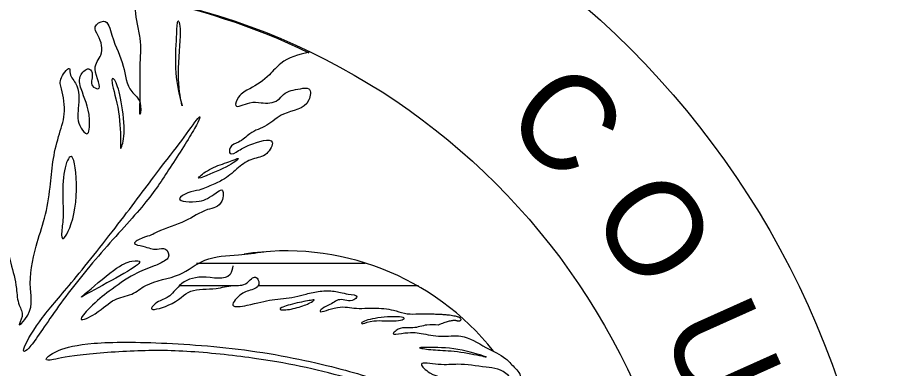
# Model space of a CAD drawing. Extents: x -1.6 to 33.4, y -12.7 to 10.9.
# Drawn here: x 27.0389 to 27.3212, y -12.2347 to -12.1203 of the extents above; entities that cross this region are included whole.
import ezdxf

# ---------------------------------------------------------------- set-up
doc = ezdxf.new("R2010")
doc.units = 0
doc.layers.add('Default', color=7, linetype='Continuous')

msp = doc.modelspace()

# ---------------------------------------------------------------- linework, layer by layer
at = {"layer": 'Default'}
for p, q in [((27.097185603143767, -12.200330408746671), (27.152113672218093, -12.200329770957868)), ((27.09167917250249, -12.20764956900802), (27.109073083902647, -12.207644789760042)), ((27.117312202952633, -12.207663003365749), (27.169493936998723, -12.207648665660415))]:
    msp.add_line(p, q, dxfattribs=at)
for radius in [0.28240568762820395, 0.2204114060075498]:
    msp.add_circle((27.03883012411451, -12.330318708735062), radius, dxfattribs=at)
for centre, radius, start, end in [((27.03811594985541, -12.33045840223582), 0.2204114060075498, 64.23515824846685, 79.6893776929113), ((27.12638568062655, -12.2824678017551), 0.08611740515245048, 38.42000269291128, 99.14313602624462)]:
    msp.add_arc(centre, radius, start, end, dxfattribs=at)
for points in [[(26.965344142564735, -12.171041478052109), (26.962602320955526, -12.165534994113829), (26.958024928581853, -12.16095770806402), (26.951621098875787, -12.155478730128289), (26.947945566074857, -12.153629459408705), (26.947954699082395, -12.151798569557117), (26.951616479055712, -12.151816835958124), (26.95893113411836, -12.153638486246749), (26.968094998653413, -12.156384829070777), (26.971752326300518, -12.157295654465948), (26.9754279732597, -12.159122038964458), (26.978169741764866, -12.160051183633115), (26.979080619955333, -12.160971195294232), (26.981817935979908, -12.162792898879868), (26.98000074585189, -12.160037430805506), (26.978165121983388, -12.156389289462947), (26.97540960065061, -12.153629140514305), (26.973587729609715, -12.151812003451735), (26.974512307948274, -12.14998568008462), (26.976338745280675, -12.150887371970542), (26.983648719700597, -12.153647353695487), (26.99099088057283, -12.159131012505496), (26.995563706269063, -12.164623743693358), (26.99831477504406, -12.168276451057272), (27.00196280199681, -12.16646371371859), (27.000136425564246, -12.160961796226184), (26.998305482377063, -12.156375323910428), (26.995568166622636, -12.154553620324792), (26.994638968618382, -12.152718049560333), (26.99647442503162, -12.151811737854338), (27.00288738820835, -12.155459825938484), (27.009291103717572, -12.160961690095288), (27.014774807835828, -12.167374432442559), (27.017525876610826, -12.171027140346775), (27.021197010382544, -12.178346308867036), (27.022098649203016, -12.171942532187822), (27.021187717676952, -12.166445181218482), (27.01935209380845, -12.162797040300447), (27.017530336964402, -12.160957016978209), (27.018454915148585, -12.159130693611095), (27.022112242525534, -12.16004151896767), (27.02668968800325, -12.169196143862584), (27.03127175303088, -12.182012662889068), (27.033999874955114, -12.190265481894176), (27.036764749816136, -12.200326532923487), (27.03857742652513, -12.208574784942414), (27.039511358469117, -12.214049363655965), (27.04040853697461, -12.217715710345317), (27.039502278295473, -12.220457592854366), (27.041342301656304, -12.218635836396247), (27.043154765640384, -12.208574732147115), (27.04498561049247, -12.194828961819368), (27.047731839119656, -12.185687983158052), (27.04956730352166, -12.175604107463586), (27.05047807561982, -12.167369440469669), (27.052327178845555, -12.159139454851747), (27.054148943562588, -12.151801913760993), (27.053228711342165, -12.143581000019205), (27.053224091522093, -12.139919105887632), (27.055984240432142, -12.137163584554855), (27.055979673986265, -12.138079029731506), (27.057815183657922, -12.141750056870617), (27.05873541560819, -12.149970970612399), (27.059641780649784, -12.15638376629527), (27.061463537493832, -12.158223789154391), (27.062378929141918, -12.15365101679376), (27.059637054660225, -12.143567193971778), (27.059637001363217, -12.138989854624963), (27.062392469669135, -12.13717266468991), (27.063298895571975, -12.138985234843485), (27.06330351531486, -12.142647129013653), (27.065129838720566, -12.143571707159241), (27.064223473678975, -12.137158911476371), (27.066054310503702, -12.132590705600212), (27.065125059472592, -12.126177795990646), (27.06422331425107, -12.123426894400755), (27.06695589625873, -12.121609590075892), (27.069702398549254, -12.126177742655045), (27.073382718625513, -12.136243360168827), (27.0761108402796, -12.144496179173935), (27.0788619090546, -12.148148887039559), (27.078866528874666, -12.151810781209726), (27.078875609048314, -12.145402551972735), (27.078875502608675, -12.136247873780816), (27.078875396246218, -12.12709319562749), (27.07795989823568, -12.122511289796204), (27.077044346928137, -12.113352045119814)], [(27.13380351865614, -12.131669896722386), (27.124630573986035, -12.13533178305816), (27.120973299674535, -12.138998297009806), (27.11456512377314, -12.143566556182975), (27.110912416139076, -12.146317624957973), (27.109983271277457, -12.149059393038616), (27.11456517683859, -12.148143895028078), (27.118227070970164, -12.148139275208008), (27.123724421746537, -12.147228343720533), (27.125564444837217, -12.145406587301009), (27.131043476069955, -12.143580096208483), (27.13378992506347, -12.14357090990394), (27.133794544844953, -12.147232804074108), (27.12555536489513, -12.15181481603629), (27.12006720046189, -12.1554721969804), (27.114560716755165, -12.158214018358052), (27.11090800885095, -12.160965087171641), (27.10815242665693, -12.162805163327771), (27.108166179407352, -12.164636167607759), (27.110917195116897, -12.163711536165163), (27.114565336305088, -12.16187591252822), (27.121893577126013, -12.160974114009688), (27.120067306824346, -12.164626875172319), (27.11548083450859, -12.166457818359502), (27.11091268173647, -12.169204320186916), (27.106339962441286, -12.172866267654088), (27.102668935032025, -12.174701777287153), (27.098082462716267, -12.176532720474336), (27.09443888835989, -12.17745289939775), (27.091683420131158, -12.179270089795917), (27.09808708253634, -12.180194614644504), (27.100838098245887, -12.179269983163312), (27.103593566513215, -12.177452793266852), (27.1054062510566, -12.176523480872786), (27.105410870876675, -12.18018537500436), (27.100842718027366, -12.182931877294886), (27.093523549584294, -12.186603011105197), (27.08435060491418, -12.190264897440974), (27.082538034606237, -12.191171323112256), (27.07978701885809, -12.192095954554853), (27.077031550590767, -12.19391314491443), (27.079773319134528, -12.194842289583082), (27.084368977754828, -12.195757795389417), (27.087115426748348, -12.195748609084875), (27.088017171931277, -12.198499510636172), (27.08709716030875, -12.199410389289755), (27.08344901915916, -12.201246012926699), (27.07702709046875, -12.203983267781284), (27.068806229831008, -12.209480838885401), (27.062393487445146, -12.214964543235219), (27.059651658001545, -12.218635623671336), (27.064215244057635, -12.216804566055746), (27.070623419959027, -12.212236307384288), (27.07612545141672, -12.2103870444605), (27.080693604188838, -12.207640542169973), (27.091674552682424, -12.203987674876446), (27.09991373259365, -12.19940566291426), (27.110908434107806, -12.197583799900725), (27.119152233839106, -12.196663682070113)], [(27.109082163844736, -12.201236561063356), (27.108152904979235, -12.204001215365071), (27.09901666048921, -12.204893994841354), (27.09167917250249, -12.20764956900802), (27.088021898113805, -12.211316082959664), (27.084350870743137, -12.213151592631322), (27.082533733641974, -12.214973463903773), (27.088031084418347, -12.214062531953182), (27.095354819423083, -12.20947595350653), (27.103575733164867, -12.20855572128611), (27.109073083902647, -12.207644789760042), (27.113654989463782, -12.206729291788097), (27.11641045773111, -12.204912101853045), (27.117321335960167, -12.205832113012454), (27.117312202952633, -12.207663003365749), (27.113664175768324, -12.209475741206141), (27.111828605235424, -12.210404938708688), (27.10908688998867, -12.214053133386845), (27.113664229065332, -12.214053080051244), (27.121889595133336, -12.212240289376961), (27.129217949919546, -12.211315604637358), (27.132884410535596, -12.210395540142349), (27.137466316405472, -12.209480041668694), (27.142043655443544, -12.209479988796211), (27.146616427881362, -12.210395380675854), (27.14935819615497, -12.211324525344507), (27.14843818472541, -12.212235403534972), (27.14386084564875, -12.212235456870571), (27.140212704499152, -12.214071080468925), (27.13837724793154, -12.214977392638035), (27.137457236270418, -12.2158882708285), (27.142039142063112, -12.214972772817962), (27.14844737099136, -12.214981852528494), (27.155771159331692, -12.21497261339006), (27.16217482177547, -12.215897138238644), (27.165832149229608, -12.216807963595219), (27.16949404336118, -12.216803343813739)], [(27.17590689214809, -12.22047431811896), (27.172244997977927, -12.220478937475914), (27.1676630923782, -12.221394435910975), (27.164916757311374, -12.22138073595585), (27.162165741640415, -12.22230536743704), (27.161245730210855, -12.2232162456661), (27.163992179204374, -12.223207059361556), (27.170400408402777, -12.223216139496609), (27.17682695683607, -12.224140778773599), (27.183235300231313, -12.224126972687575), (27.191456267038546, -12.227784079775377), (27.197869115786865, -12.231455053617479), (27.200624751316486, -12.23419231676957), (27.20246026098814, -12.237863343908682), (27.201540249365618, -12.23877422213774), (27.19878004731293, -12.23695240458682), (27.191470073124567, -12.23419242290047), (27.18231996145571, -12.233277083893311), (27.175911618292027, -12.233290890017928), (27.170418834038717, -12.23328637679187), (27.17315158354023, -12.236023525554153), (27.180489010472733, -12.23786817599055), (27.18688822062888, -12.239685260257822), (27.195131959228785, -12.243365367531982), (27.203366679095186, -12.24885347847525), (27.208864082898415, -12.252519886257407), (27.21161515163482, -12.256172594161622), (27.215258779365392, -12.259829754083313), (27.215272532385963, -12.261660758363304), (27.212516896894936, -12.258923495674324), (27.204286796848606, -12.25709727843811), (27.19787394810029, -12.25342630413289), (27.194221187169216, -12.251600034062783), (27.192385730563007, -12.25250634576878), (27.199714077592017, -12.260759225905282), (27.204286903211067, -12.266251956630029), (27.210681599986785, -12.273561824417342), (27.214348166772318, -12.281796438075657), (27.217108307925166, -12.288218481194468), (27.21802380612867, -12.292800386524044), (27.218010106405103, -12.295546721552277), (27.217094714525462, -12.30011949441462), (27.215259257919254, -12.301025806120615), (27.213446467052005, -12.292800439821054), (27.20428706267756, -12.279983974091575), (27.19878503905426, -12.272655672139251), (27.189634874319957, -12.26716299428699), (27.189630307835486, -12.268078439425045), (27.19328768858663, -12.27356660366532), (27.19879884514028, -12.279064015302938), (27.2015453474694, -12.28363216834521), (27.20335797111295, -12.287303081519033), (27.203371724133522, -12.289134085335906), (27.202442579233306, -12.291875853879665), (27.196958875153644, -12.2854631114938), (27.191456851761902, -12.27813480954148), (27.184146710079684, -12.2708203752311), (27.17864930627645, -12.267153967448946), (27.174996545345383, -12.265327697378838), (27.176827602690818, -12.269891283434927), (27.176827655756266, -12.27446862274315), (27.179560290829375, -12.27722865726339), (27.177734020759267, -12.28088141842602), (27.17590301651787, -12.280895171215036), (27.169490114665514, -12.272646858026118), (27.16217997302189, -12.265332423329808), (27.15758426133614, -12.259839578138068), (27.15209142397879, -12.255257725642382), (27.14843409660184, -12.254346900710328), (27.145696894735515, -12.25250231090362), (27.144786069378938, -12.2561596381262), (27.14753245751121, -12.260750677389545), (27.149345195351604, -12.264398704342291), (27.15118070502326, -12.2680697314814), (27.150274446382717, -12.270811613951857), (27.148443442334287, -12.270825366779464), (27.145697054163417, -12.266234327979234), (27.140208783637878, -12.260737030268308), (27.13013843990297, -12.251600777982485), (27.12555648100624, -12.247938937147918), (27.121899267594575, -12.24700522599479), (27.119157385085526, -12.246098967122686), (27.12005913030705, -12.248849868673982), (27.124636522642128, -12.253427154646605), (27.127392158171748, -12.256164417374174), (27.12920478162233, -12.259835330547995), (27.129213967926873, -12.262581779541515), (27.124641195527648, -12.261666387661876), (27.119134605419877, -12.255253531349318), (27.11365552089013, -12.252502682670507), (27.105416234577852, -12.247930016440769)], [(27.17590689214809, -12.22047431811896), (27.172244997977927, -12.220478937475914), (27.1676630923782, -12.221394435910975), (27.164916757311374, -12.22138073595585), (27.162165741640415, -12.22230536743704), (27.161245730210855, -12.2232162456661), (27.163992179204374, -12.223207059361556), (27.170400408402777, -12.223216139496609), (27.17682695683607, -12.224140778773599), (27.183235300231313, -12.224126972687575), (27.191456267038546, -12.227784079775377), (27.197869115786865, -12.231455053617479), (27.200624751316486, -12.23419231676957), (27.20246026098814, -12.237863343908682), (27.201540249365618, -12.23877422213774), (27.19878004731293, -12.23695240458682), (27.191470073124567, -12.23419242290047), (27.18231996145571, -12.233277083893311), (27.175911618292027, -12.233290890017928), (27.170418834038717, -12.23328637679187), (27.17315158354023, -12.236023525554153), (27.180489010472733, -12.23786817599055), (27.18688822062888, -12.239685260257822), (27.195131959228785, -12.243365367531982), (27.203366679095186, -12.24885347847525), (27.208864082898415, -12.252519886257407), (27.21161515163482, -12.256172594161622), (27.215258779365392, -12.259829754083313), (27.215272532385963, -12.261660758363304), (27.212516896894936, -12.258923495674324), (27.204286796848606, -12.25709727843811), (27.19787394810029, -12.25342630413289), (27.194221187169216, -12.251600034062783), (27.192385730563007, -12.25250634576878), (27.199714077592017, -12.260759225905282), (27.204286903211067, -12.266251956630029), (27.210681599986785, -12.273561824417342), (27.214348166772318, -12.281796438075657), (27.217108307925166, -12.288218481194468), (27.21802380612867, -12.292800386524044), (27.218010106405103, -12.295546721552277), (27.217094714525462, -12.30011949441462), (27.215259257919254, -12.301025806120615), (27.213446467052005, -12.292800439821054), (27.20428706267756, -12.279983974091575), (27.19878503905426, -12.272655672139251), (27.189634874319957, -12.26716299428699), (27.189630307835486, -12.268078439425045), (27.19328768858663, -12.27356660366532), (27.19879884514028, -12.279064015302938), (27.2015453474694, -12.28363216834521), (27.20335797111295, -12.287303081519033), (27.203371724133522, -12.289134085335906), (27.202442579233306, -12.291875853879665), (27.196958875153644, -12.2854631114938), (27.191456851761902, -12.27813480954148), (27.184146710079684, -12.2708203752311), (27.17864930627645, -12.267153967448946), (27.174996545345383, -12.265327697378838), (27.176827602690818, -12.269891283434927), (27.176827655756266, -12.27446862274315), (27.179560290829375, -12.27722865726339), (27.177734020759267, -12.28088141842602), (27.17590301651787, -12.280895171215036), (27.169490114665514, -12.272646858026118), (27.16217997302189, -12.265332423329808), (27.15758426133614, -12.259839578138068), (27.15209142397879, -12.255257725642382), (27.14843409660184, -12.254346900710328), (27.145696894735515, -12.25250231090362), (27.144786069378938, -12.2561596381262), (27.14753245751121, -12.260750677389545), (27.149345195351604, -12.264398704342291), (27.15118070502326, -12.2680697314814), (27.150274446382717, -12.270811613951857), (27.148443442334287, -12.270825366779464), (27.145697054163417, -12.266234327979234), (27.140208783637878, -12.260737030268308), (27.13013843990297, -12.251600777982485), (27.12555648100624, -12.247938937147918), (27.121899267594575, -12.24700522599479), (27.119157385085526, -12.246098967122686), (27.12005913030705, -12.248849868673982), (27.124636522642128, -12.253427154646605), (27.127392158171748, -12.256164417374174), (27.12920478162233, -12.259835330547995), (27.129213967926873, -12.262581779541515), (27.124641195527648, -12.261666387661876), (27.119134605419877, -12.255253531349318), (27.11365552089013, -12.252502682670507), (27.105416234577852, -12.247930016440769)]]:
    msp.add_spline(points, degree=3, dxfattribs=at)
for points, degree in [([(27.09229640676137, -12.1481472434), (27.09260157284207, -12.149674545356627), (27.092589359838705, -12.149064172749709), (27.089847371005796, -12.139003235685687), (27.090762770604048, -12.125252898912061), (27.090762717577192, -12.12067555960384), (27.092607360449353, -12.122515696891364), (27.090758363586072, -12.13990036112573), (27.091991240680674, -12.146619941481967), (27.09229640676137, -12.1481472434)], 3), ([(27.072766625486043, -12.162636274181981), (27.072461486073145, -12.163397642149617), (27.07244927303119, -12.162787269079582), (27.0724628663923, -12.150886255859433), (27.068787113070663, -12.139905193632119), (27.07061800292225, -12.139914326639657), (27.072467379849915, -12.145393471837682), (27.07428010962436, -12.158219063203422), (27.073071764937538, -12.161874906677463), (27.072766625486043, -12.162636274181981)], 3), ([(27.041179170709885, -12.227633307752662), (27.04041782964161, -12.229616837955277), (27.042248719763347, -12.229625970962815), (27.051407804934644, -12.21497840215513), (27.06605505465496, -12.196673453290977), (27.081608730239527, -12.180181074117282), (27.088021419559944, -12.170120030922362), (27.09810051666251, -12.154561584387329), (27.09901134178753, -12.150904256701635), (27.09352323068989, -12.15913897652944), (27.086199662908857, -12.16828000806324), (27.073364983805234, -12.185678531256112), (27.055975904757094, -12.2076545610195), (27.04681676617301, -12.21772479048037), (27.041940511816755, -12.225649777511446), (27.041179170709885, -12.227633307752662)], 3), ([(27.053381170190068, -12.189484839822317), (27.05353448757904, -12.187807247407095), (27.05414474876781, -12.1847587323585), (27.053233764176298, -12.174684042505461), (27.055064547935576, -12.165538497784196), (27.05781556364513, -12.164613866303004), (27.0587266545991, -12.183843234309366), (27.053224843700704, -12.19482428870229), (27.053227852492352, -12.19116243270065), (27.053381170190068, -12.189484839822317)], 3), ([(27.098099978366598, -12.172256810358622), (27.097490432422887, -12.172867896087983), (27.098100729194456, -12.172870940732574), (27.109086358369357, -12.168279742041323), (27.11182350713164, -12.165546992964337), (27.108152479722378, -12.167382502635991), (27.10175800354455, -12.169204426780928), (27.098709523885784, -12.171645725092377), (27.098099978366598, -12.172256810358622)], 3), ([(27.061013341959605, -12.210239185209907), (27.059029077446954, -12.21191908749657), (27.05964241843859, -12.211311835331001), (27.07336519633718, -12.203987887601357), (27.080688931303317, -12.199401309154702), (27.076111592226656, -12.199401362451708), (27.071548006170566, -12.201232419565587), (27.062997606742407, -12.208559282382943), (27.061013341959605, -12.210239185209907)], 3), ([(27.12540507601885, -12.215587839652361), (27.124337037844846, -12.215586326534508), (27.12372978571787, -12.21497298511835), (27.130124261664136, -12.21315106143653), (27.135621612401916, -12.21224012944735), (27.135621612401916, -12.21224012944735), (27.13470160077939, -12.213151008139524), (27.13013801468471, -12.214982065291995), (27.126473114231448, -12.21558935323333), (27.12540507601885, -12.215587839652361)], 3), ([(27.16949404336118, -12.216803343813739), (27.176817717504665, -12.216816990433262), (27.18322149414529, -12.217718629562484), (27.183235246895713, -12.219549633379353), (27.18047047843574, -12.218643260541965), (27.17590689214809, -12.22047431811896)], 2), ([(27.151492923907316, -12.220009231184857), (27.15088568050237, -12.22015878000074), (27.15027842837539, -12.2195454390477), (27.156672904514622, -12.217723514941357), (27.16674302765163, -12.217727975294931), (27.163094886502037, -12.21956359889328), (27.153921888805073, -12.218648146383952), (27.152100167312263, -12.219859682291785), (27.151492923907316, -12.220009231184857)], 3), ([(27.048500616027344, -12.231152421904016), (27.048043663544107, -12.231760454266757), (27.04866624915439, -12.23235861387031), (27.055060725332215, -12.230536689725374), (27.07612566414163, -12.228696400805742), (27.094435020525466, -12.228696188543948), (27.11822346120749, -12.231446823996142), (27.13288010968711, -12.234197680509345), (27.147532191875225, -12.237863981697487), (27.162179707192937, -12.242445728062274), (27.16765879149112, -12.245196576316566), (27.170400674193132, -12.246102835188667), (27.162165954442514, -12.24061472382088), (27.15026488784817, -12.236023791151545), (27.119152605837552, -12.2287050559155), (27.086186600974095, -12.225954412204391), (27.061468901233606, -12.225968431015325), (27.051407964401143, -12.22871041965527), (27.04895756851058, -12.230544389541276), (27.048500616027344, -12.231152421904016)], 3), ([(27.169945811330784, -12.22793997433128), (27.169485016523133, -12.227788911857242), (27.17131590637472, -12.227798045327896), (27.18230158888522, -12.227784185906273), (27.193291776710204, -12.231455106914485), (27.190549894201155, -12.230548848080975), (27.180488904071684, -12.228713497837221), (27.174080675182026, -12.228704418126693), (27.170406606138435, -12.22809103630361), (27.169945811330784, -12.22793997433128)], 3)]:
    msp.add_open_spline(points, degree=degree, dxfattribs=at)

# ---------------------------------------------------------------- texts
for s, height, rotation, p in [('C', 0.03099552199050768, 315.6404999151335, (27.196055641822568, -12.154546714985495)), ('O', 0.03099552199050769, 304.9015582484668, (27.224421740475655, -12.184761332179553)), ('U', 0.03099552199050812, 294.1626165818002, (27.24822430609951, -12.221384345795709))]:
    msp.add_text(s, height=height, rotation=rotation, dxfattribs=at).set_placement(p)

doc.saveas('drawing.dxf')
